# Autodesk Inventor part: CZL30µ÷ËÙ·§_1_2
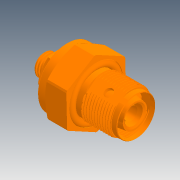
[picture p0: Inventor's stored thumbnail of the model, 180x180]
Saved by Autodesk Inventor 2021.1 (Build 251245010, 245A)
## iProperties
Created: 2021-05
Part Number: CZL30µ÷ËÙ·§_1_2
Material: Ogólny
Document SubType Name: Modeling
Designer: user
Density: 1 g/cm^3
Appearance: Domyślna
Author: user
Revision Number: ÈÎºÎ
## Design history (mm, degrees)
feature "Złożony1"
body "Srf1"
